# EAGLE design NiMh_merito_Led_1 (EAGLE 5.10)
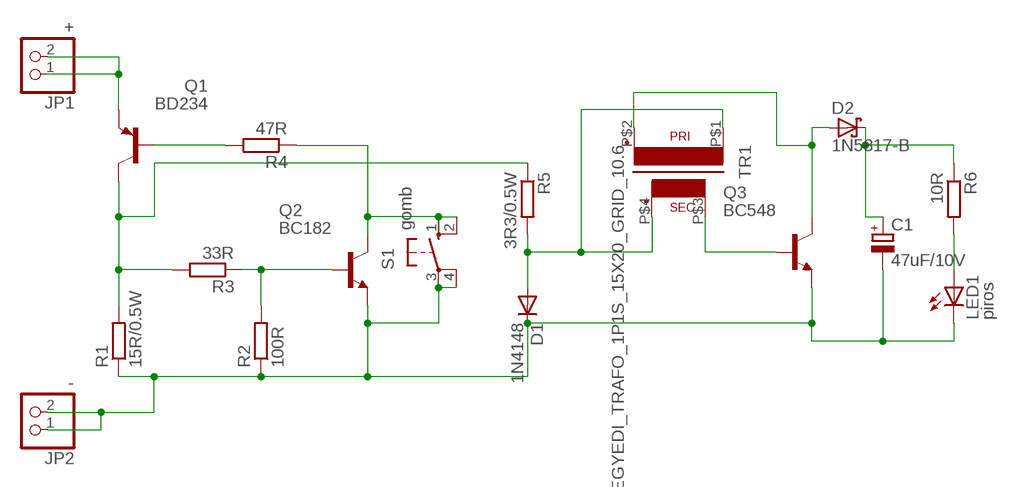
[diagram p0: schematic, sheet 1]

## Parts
C1  47uF/10V  CPOL-EUE5-8.5  [E5-8,5]
D1  1N4148  1N4148DO35-7  [DO35-7]
D2  1N5817-B  [DO41-7.6]
JP1  +  PINHD-1X2  [1X02]
JP2  -  PINHD-1X2  [1X02]
LED1  piros  LED3MM  [LED3MM]
Q1  BD234  BD236  [TO126]
Q2  BC182  BC548  [TO92-EBC]
Q3  BC548  [TO92-EBC]
R1  15R/0.5W  R-EU_0411/15  [0411/15]
R2  100R  R-EU_0207/10  [0207/10]
R3  33R  R-EU_0207/10  [0207/10]
R4  47R  R-EU_0207/10  [0207/10]
R5  3R3/0.5W  R-EU_0411/15  [0411/15]
R6  10R  R-EU_0207/10  [0207/10]
S1  gomb  10-XX  [B3F-10XX]
TR1  EGYEDI_TRAFO_1P1S_15X20_GRID_10.6  [EGYEDI_TRAFO_15X20_GRID:10.6]

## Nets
N$1: Q1.2(C) R1.2 R3.2 R5.1
N$2: Q2.B R2.2 R3.1
N$3: Q1.3(B) R4.2
N$4: JP1.1 JP1.2 Q1.1(E)
N$5: Q2.C R4.1 S1.1(S) S1.2(S1)
N$6: LED1.A R6.2
N$7: C1.- D1.C JP2.1 JP2.2 LED1.K(C) Q2.E Q3.E R1.1 R2.1 S1.3(P) S1.4(P1)
N$8: D1.A R5.2 TR1.P$1(P1) TR1.P$4(S3)
N$9: Q3.B TR1.P$3(S4)
N$11: D2.A Q3.C TR1.P$2(P2)
N$12: C1.+ D2.C R6.1

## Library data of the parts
C1 = rcl:CPOL-EU: POLARIZED CAPACITOR, European symbol
D1 = diode:1N4148: DIODE
D2 = diode:1N581*: 1.0A SCHOTTKY BARRIER RECTIFIER
JP1 JP2 = pinhead:PINHD-1X2: PIN HEADER
LED1 = led:LED: LED
Q1 = transistor-pnp:BD236: PNP Transistor
Q2 Q3 = transistor-npn:BC548*: NPN Transistor
R1 R5 = resistor:R-EU_: RESISTOR, European symbol
R2-R4 R6 = rcl:R-EU_: RESISTOR, European symbol
S1 = switch-omron:10-XX: OMRON SWITCH
TR1 = Schalk_sajat:EGYEDI_TRAFO_1P1S_15X20_GRID_10.6

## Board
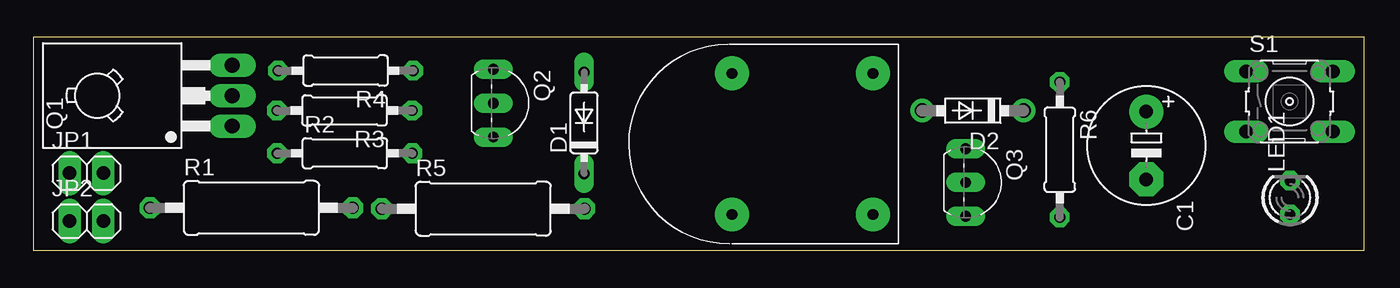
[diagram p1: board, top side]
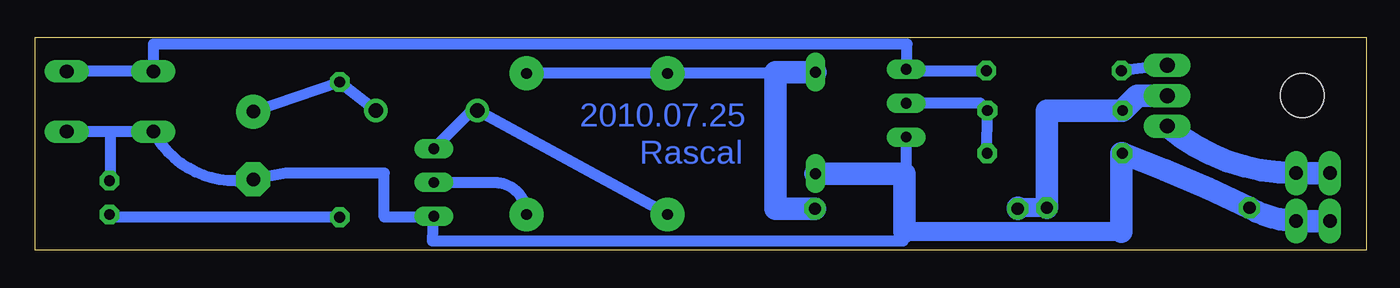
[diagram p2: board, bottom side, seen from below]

Size 100 x 16 mm. Coordinates in mm from the lower left corner, seen from the top.
Outline: 0,0 100,0 100,16 0,16 0,0
Copper layers (1*16): Top 0.035mm / dielectric 1.5mm / Bottom 0.035mm
Design rules "default *": minimum track width 10mil, minimum drill 24mil, track to track 8mil, track to pad 8mil, pad to pad 8mil, via to via 8mil, smd to smd 8mil, copper to edge 40mil, drill to drill 8mil, minimum pad ring 13mil, minimum via ring 13mil, stop-mask expansion 4mil, vias tented up to drill 0mil, thermal gap 10mil

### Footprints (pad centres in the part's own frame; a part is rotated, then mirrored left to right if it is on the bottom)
E5-8,5 = drill 1.016 pad 2.54 round: + -2.54,0 | drill 1.016 pad 2.54 octagon: - 2.54,0
DO35-7 = drill 0.813 long: A 3.81,0; C -3.81,0
DO41-7.6 = drill 1.1 pad 1.7 round: A 3.81,0; C -3.81,0
1X02 = drill 1.016 long: 1 -1.27,0; 2 1.27,0
LED3MM = drill 0.813 octagon: A -1.27,0; K 1.27,0
TO126 = drill 1.118 long: 1 -2.286,-5.08; 2 0,-5.08; 3 2.286,-5.08 | hole 3.302: 0,5.08
TO92-EBC = drill 0.813 long: B 0,-1.27; C -2.54,-1.27; E 2.54,-1.27
0411/15 = drill 0.914 octagon: 1 -7.62,0; 2 7.62,0
0207/10 = drill 0.813 octagon: 1 -5.08,0; 2 5.08,0
B3F-10XX = drill 1.016 long: 1 -3.251,2.261; 2 3.251,2.261; 3 -3.251,-2.261; 4 3.251,-2.261
EGYEDI_TRAFO_15X20_GRID:10.6 = drill 0.8 pad 2.54 round: P$1 0,5.3; P$2 0,-5.3; P$3 10.6,-5.3; P$4 10.6,5.3

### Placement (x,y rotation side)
C1  83.64,7.88 270 top
D1  41.39,9.58 90 top
D2  70.6,10.5 180 top
JP1  4,5.8 0 top
JP2  4,2.2 0 top
LED1  94.44,3.97 90 top
Q1  9.88,11.63 90 top
Q2  35.84,11.06 270 top
Q3  71.34,5.11 270 top
R1  16.39,3.2 0 top
R2  23.41,7.3 0 top
R3  23.39,10.51 180 top
R4  23.47,13.51 180 top
R5  33.81,3.14 0 top
R6  77.14,7.57 270 top
S1  94.4,11.19 0 top
TR1  52.5,8 0 top

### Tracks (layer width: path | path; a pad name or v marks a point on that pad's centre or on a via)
N$1
  Bottom 1.422: R1.2 26.19,3.2
  Bottom 1.676: Q1.2 17.19,11.63 R3.2 24.01,10.51 R1.2 | 26.19,3.2 R5.1
N$2
  Bottom 0.813: R2.2 R3.1 29.02,11.06 Q2.B
N$3
  Bottom 0.813: Q1.3 R4.2
N$4
  Bottom 1.676: JP1.1 JP1.2 arc40 Q1.1
N$5
  Bottom 0.813: S1.2 S1.1 91.15,15.5 34.5,15.5 34.5,13.6 Q2.C 34.57,13.51 R4.1
N$6
  Bottom 0.813: R6.2 94.44,2.49 LED1.A
N$7
  Bottom 0.254: Q3.E 70.5,2.5
  Bottom 0.406: 34.7,1.4 34.8,0.7
  Bottom 0.813: Q3.E 70.17,0.7 34.8,0.7 | 34.7,5.77 34.57,5.77 Q2.E | S1.3 91.15,8.5 | S1.3 94.4,8.93 | 94.4,8.93 S1.4 | LED1.K 94.4,5.24 94.4,8.93 | 70.5,2.5 73.8,2.5 73.8,5.8 81.2,5.8 C1.- arc72 S1.3
  Bottom 1.422: 18.4,1.4 34.7,1.4
  Bottom 1.676: JP2.1 JP2.2 arc26 R1.1 arc-5 R2.1 18.4,7.3 18.4,1.4 | D1.C 34.7,5.77 34.7,1.4
N$8
  Bottom 0.813: D1.A 41.39,13.3 TR1.P$1 TR1.P$4
  Bottom 1.676: R5.2 44.4,3.14 44.4,13.39 D1.A
N$9
  Bottom 0.813: Q3.B 65.51,5.11 arc90 TR1.P$3
N$11
  Bottom 0.813: TR1.P$2 D2.A 67.22,10.5 Q3.C
N$12
  Bottom 0.813: C1.+ R6.1 D2.C

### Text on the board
Bottom: 2010.07.25 | Rascal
